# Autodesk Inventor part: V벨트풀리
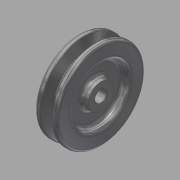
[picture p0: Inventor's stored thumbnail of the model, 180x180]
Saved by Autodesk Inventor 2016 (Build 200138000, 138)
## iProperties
Created: 2015-11
Part Number: V벨트풀리
Material: 강철, 탄소
Document SubType Name: Modeling
Designer: mduedu
Density: 1 g/cm^3
Appearance: 반광택
Author: mduedu
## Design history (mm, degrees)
sketch "스케치1"
  geometry: L1 (-9.5, 0)-(9.5, 0); L2 (0, 0)-(0, 37.7); L3 (-4.825, 37.7)-(-9.5, 37.7); L4 (-9.5, 37.7)-(-9.5, 0); L5 (0, 28.7)-(-2.074, 28.7); L6 (-2.074, 28.7)-(-4.825, 37.7); L7 (4.825, 37.7)-(9.5, 37.7); L8 (9.5, 37.7)-(9.5, 0); L9 (0, 28.7)-(2.074, 28.7); L10 (2.074, 28.7)-(4.825, 37.7); L11 (-9.5, 35)-(9.5, 35); 3 further points
  constraints: 22 end point, 7 point on line, 4 perpendicular, 3 symmetric about line, 1 coincident, 1 horizontal, 1 horizontal alignment, 1 midpoint, 1 vertical
  dimensions: "d0" = 19 distance of L1.start L1.end; "d2" = 75.4 diameter of L2.end L1 (derived); "d3" = 34 deg angle of L10 L6; "d4" = 6.3 distance between parallel lines of L11 L9; "d5" = 2.7 distance between parallel lines of L7 L11; "d6" = 8 distance of point (4, 35) point (-4, 35); "d7" = 70 diameter of L11 L1
revolve "회전1" sketch "스케치1" stored, may be unused: angle "d8" = 90 deg
sketch "스케치2"
  geometry: C1 r 24 at (0, 0); C2 r 11 at (0, 0); 1 further point
  constraints: 2 centre point, 2 coincident
  dimensions: "d9" = 48 diameter of C1; "d10" = 22 diameter of C2
extrude "돌출1" cut sketch "스케치2" distance "d11" = 6; taper "d12" = 0 deg
fillet "모깎기1" dims "d13" = 3
fillet "모깎기2" dims "d14" = 3
fillet "모깎기3" dims "d15" = 1, "d16" = 0.5, "d17" = 2
hole "구멍1" diameter "d20" = 10; stored, may be unused: countersink angle "d24" = 90 deg, drill point angle "d26" = 118 deg; dims "d18" = 10, "d19" = 10, "d21" = 6, "d22" = 4, "d23" = 2, "d25" = 8
sketch "스케치3"
  geometry: L1 (-1.5, 0)-(1.5, 0); L2 (1.5, 0)-(1.5, 6.4); L3 (1.5, 6.4)-(-1.5, 6.4); L4 (-1.5, 6.4)-(-1.5, 0); 2 further points
  constraints: 8 end point, 2 parallel, 1 coincident, 1 horizontal, 1 midpoint, 1 perpendicular
  dimensions: "d27" = 3 distance of L2.end L3.end; "d29" = 6.4 distance of L3.end L1.start
extrude "돌출2" cut sketch "스케치3" stored distance "d30" = 6; taper "d31" = 0 deg
chamfer "모따기1" distance "d32" = 0.5; stored, may be unused: second distance "d33" = 2, angle "d34" = 45 deg
node "솔리드1"
mirror "대칭1"
